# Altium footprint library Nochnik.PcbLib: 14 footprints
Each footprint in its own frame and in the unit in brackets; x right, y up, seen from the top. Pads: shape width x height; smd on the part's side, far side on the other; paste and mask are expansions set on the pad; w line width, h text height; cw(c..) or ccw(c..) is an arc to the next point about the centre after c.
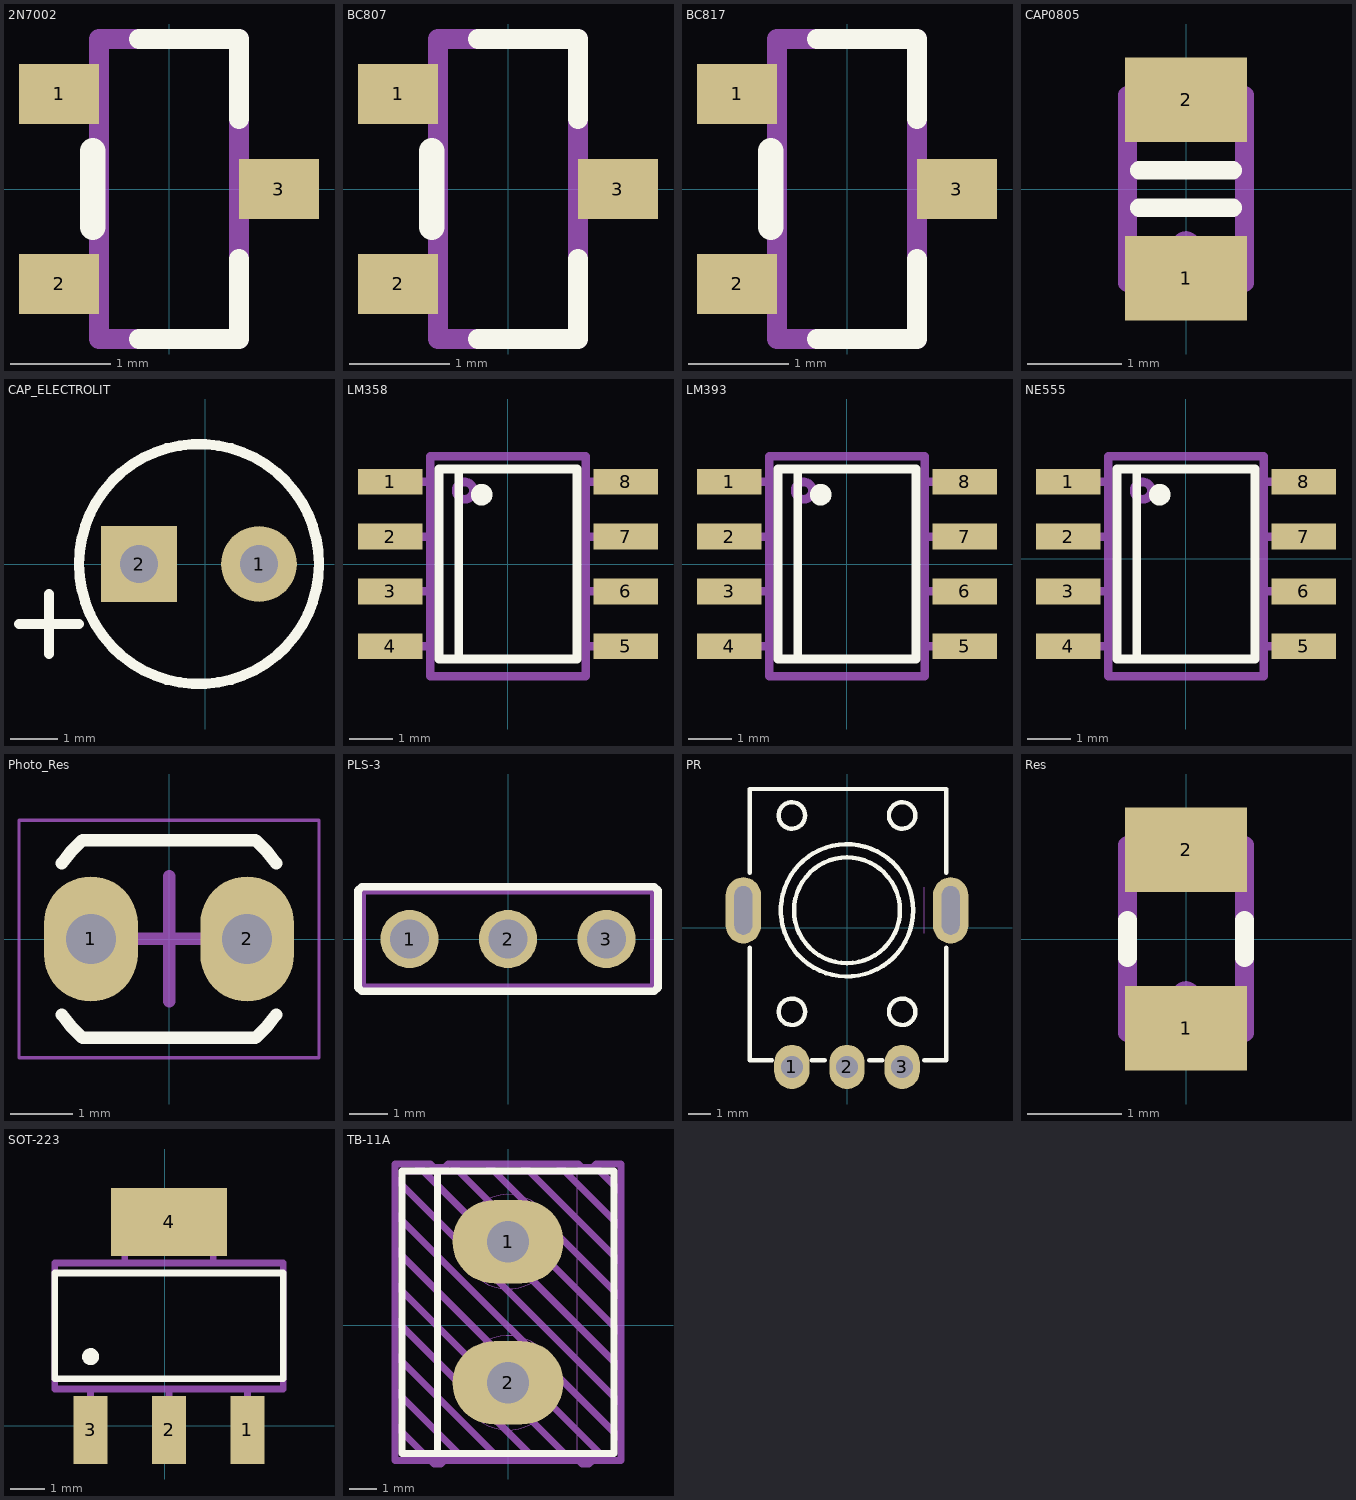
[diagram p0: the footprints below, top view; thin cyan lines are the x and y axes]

## 2N7002 [mm]
pads (3):
  rect 0.8x0.6 smd: 1(-1.1,0.95) 2(-1.1,-0.95) 3(1.1,0)
Top Overlay:
  lines w0.2: -0.3,-1.5 0.7,-1.5 0.7,-0.7 ; -0.3,1.5 0.7,1.5 0.7,0.7
  lines w0.254: -0.762,-0.381 -0.762,0.381
Mechanical 1:
  lines w0.2: -1.2,-0.95 -0.7,-0.95 ; -1.2,0.95 -0.7,0.95 ; 0.7,0 1.2,0 ; -0.7,-1.5 0.7,-1.5 0.7,1.5 -0.7,1.5 -0.7,-1.5
  text ".Designator" at -0.9,1.8 h0.8
3D body "SOT23.step": height 1.1, standoff 0, extent -1.25,-1.5 1.25,1.5

## BC807 [mm]
pads (3):
  rect 0.8x0.6 smd: 1(-1.1,0.95) 2(-1.1,-0.95) 3(1.1,0)
Top Overlay:
  lines w0.2: -0.3,-1.5 0.7,-1.5 0.7,-0.7 ; -0.3,1.5 0.7,1.5 0.7,0.7
  lines w0.254: -0.762,-0.381 -0.762,0.381
Mechanical 1:
  lines w0.2: -1.2,-0.95 -0.7,-0.95 ; -1.2,0.95 -0.7,0.95 ; 0.7,0 1.2,0 ; -0.7,-1.5 0.7,-1.5 0.7,1.5 -0.7,1.5 -0.7,-1.5
  text ".Designator" at -0.9,1.8 h0.8
3D body "SOT23.step": height 1.1, standoff 0, extent -1.25,-1.5 1.25,1.5

## BC817 [mm]
pads (3):
  rect 0.8x0.6 smd: 1(-1.1,0.95) 2(-1.1,-0.95) 3(1.1,0)
Top Overlay:
  lines w0.2: -0.3,-1.5 0.7,-1.5 0.7,-0.7 ; -0.3,1.5 0.7,1.5 0.7,0.7
  lines w0.254: -0.762,-0.381 -0.762,0.381
Mechanical 1:
  lines w0.2: -1.2,-0.95 -0.7,-0.95 ; -1.2,0.95 -0.7,0.95 ; 0.7,0 1.2,0 ; -0.7,-1.5 -0.7,1.5 0.7,1.5 0.7,-1.5 -0.7,-1.5
  text ".Designator" at -0.9,1.8 h0.8
3D body "SOT23.step": height 1.1, standoff 0, extent -1.25,-1.5 1.25,1.5

## CAP0805 [mm]
pads (2):
  rect 1.3x0.9 smd: 1(0,-0.95) 2(0,0.95)
Top Overlay:
  lines w0.2: -0.5,-0.2 0.5,-0.2 ; -0.5,0.2 0.5,0.2
Mechanical 1:
  circle w0.1: c0,-0.6 r0.1
  lines w0.2: -0.625,-1 0.625,-1 0.625,1 -0.625,1 -0.625,-1
  text ".Designator" at -0.7,1.5 h0.8
3D body: height 0.8, standoff 0, extent -0.675,-0.5 0.675,0.5
3D body: height 0.8, standoff 0, extent -0.675,0.5 0.675,1.05
3D body: height 0.8, standoff 0, extent -0.675,-1.05 0.675,-0.5

## CAP_ELECTROLIT [mm]
pads (2):
  round 1.6 hole 0.8: 1(1.143,0)
  rect 1.6x1.6 hole 0.8: 2(-1.397,0)
Top Overlay:
  circle w0.22: c-0.127,0 r2.54
  lines w0.22: -3.937,-1.27 -2.667,-1.27 ; -3.302,-1.905 -3.302,-0.635
3D body "User Library-Capacitor Electrolitico 5x11.step": height 11.9, standoff -1.7, extent -2.627,-2.5 2.373,2.5

## LM358 [mm]
pads (8):
  rect 1.5x0.6 smd: 1(-2.725,1.905) 2(-2.725,0.635) 3(-2.725,-0.635) 4(-2.725,-1.905) 5(2.725,-1.905) 6(2.725,-0.635) 7(2.725,0.635) 8(2.725,1.905)
Top Overlay:
  circle w0.25: c-0.608,1.605 r0.125
  lines w0.2: -1.143,-2.2 -1.143,2.2 ; -1.6,-2.2 1.6,-2.2 1.6,2.2 -1.6,2.2 -1.6,-2.2
Mechanical 1:
  circle w0.2: c-1,1.7 r0.2
  lines w0.2: -2.8,-1.905 -1.8,-1.905 ; -2.8,-0.635 -1.8,-0.635 ; -2.8,0.635 -1.8,0.635 ; -2.8,1.905 -1.8,1.905 ; 1.8,-1.905 2.8,-1.905 ; 1.8,-0.635 2.8,-0.635 ; 1.8,0.635 2.8,0.635 ; 1.8,1.905 2.8,1.905 ; -1.8,-2.6 -1.8,2.5 1.8,2.5 1.8,-2.6 -1.8,-2.6
  text ".Designator" at -1.801,2.819 h0.8
3D body "SOIC-88.step": height 1.75, standoff 0, extent -3,-2.5 3,2.5

## LM393 [mm]
pads (8):
  rect 1.5x0.6 smd: 1(-2.725,1.905) 2(-2.725,0.635) 3(-2.725,-0.635) 4(-2.725,-1.905) 5(2.725,-1.905) 6(2.725,-0.635) 7(2.725,0.635) 8(2.725,1.905)
Top Overlay:
  circle w0.25: c-0.608,1.605 r0.125
  lines w0.2: -1.143,-2.2 -1.143,2.2 ; -1.6,-2.2 -1.6,2.2 1.6,2.2 1.6,-2.2 -1.6,-2.2
Mechanical 1:
  circle w0.2: c-1,1.7 r0.2
  lines w0.2: -2.8,-1.905 -1.8,-1.905 ; -2.8,-0.635 -1.8,-0.635 ; -2.8,0.635 -1.8,0.635 ; -2.8,1.905 -1.8,1.905 ; 1.8,-1.905 2.8,-1.905 ; 1.8,-0.635 2.8,-0.635 ; 1.8,0.635 2.8,0.635 ; 1.8,1.905 2.8,1.905 ; -1.8,-2.6 1.8,-2.6 1.8,2.5 -1.8,2.5 -1.8,-2.6
  text ".Designator" at -1.801,2.819 h0.8
3D body "SOIC-88.step": height 1.75, standoff 0, extent -3,-2.5 3,2.5

## NE555 [mm]
pads (8):
  rect 1.5x0.6 smd: 1(-2.725,1.778) 2(-2.725,0.508) 3(-2.725,-0.762) 4(-2.725,-2.032) 5(2.725,-2.032) 6(2.725,-0.762) 7(2.725,0.508) 8(2.725,1.778)
Top Overlay:
  circle w0.25: c-0.608,1.478 r0.125
  lines w0.2: -1.143,-2.327 -1.143,2.073 ; -1.6,-2.327 1.6,-2.327 1.6,2.073 -1.6,2.073 -1.6,-2.327
Mechanical 1:
  circle w0.2: c-1,1.573 r0.2
  lines w0.2: -2.8,-2.032 -1.8,-2.032 ; -2.8,-0.762 -1.8,-0.762 ; -2.8,0.508 -1.8,0.508 ; -2.8,1.778 -1.8,1.778 ; 1.8,-2.032 2.8,-2.032 ; 1.8,-0.762 2.8,-0.762 ; 1.8,0.508 2.8,0.508 ; 1.8,1.778 2.8,1.778 ; -1.8,-2.727 -1.8,2.373 1.8,2.373 1.8,-2.727 -1.8,-2.727
  text ".Designator" at -1.801,2.692 h0.8
3D body "SOIC-88.step": height 1.75, standoff 0, extent -3,-2.627 3,2.373

## Photo_Res [mm]
pads (2):
  oval 1.5x2 hole 0.8: 1(-1.25,0) 2(1.25,0)
Top Overlay:
  lines w0.2: -1.716,-1.211 ccw(c0,0) -1.383,-1.58 1.383,-1.58 ccw(c0,0) 1.716,-1.211 ; -1.716,1.211 cw(c0,0) -1.383,1.58 1.383,1.58 cw(c0,0) 1.716,1.211
Mechanical 15:
  lines w0.05: -2.4,-1.9 -2.4,1.9 2.4,1.9 2.4,-1.9 -2.4,-1.9
  lines w0.2: -1,0 1,0 ; 0,-1 0,1
3D body "Advanced Photonix NSL-19M51.step": height 1.8, standoff -2.65, extent -2.15,-1.65 2.15,1.65

## PLS-3 [mm]
pads (3):
  round 1.5 hole 1: 1(-2.54,0) 2(0,0) 3(2.54,0)
Top Overlay:
  lines w0.2: -3.87,-1.25 -3.87,1.25 -3.77,1.35 3.77,1.35 3.87,1.25 3.87,-1.25 3.77,-1.35 -3.77,-1.35 -3.87,-1.25
Mechanical 1:
  lines w0.2: -3.77,-1.25 3.77,-1.25 3.77,1.25 -3.77,1.25 -3.77,-1.25
  text ".Designator" at -3.769,1.533 h0.8
3D body: height 1.25, standoff -1.5, extent 2.159,-0.318 2.921,0.318
3D body: height 1.25, standoff -1.5, extent -2.921,-0.318 -2.159,0.318
3D body: height 1.25, standoff -1.5, extent -0.381,-0.318 0.381,0.318
3D body "FEMALE-2.54-3P.SLDPRT": height 8.4, standoff 0, extent -3.71,-1.2 3.81,1.2

## PR [mm]
pads (5):
  oval 1.6x2 / inner round 1.4 / far side oval 1.6x2 hole 1: 1(-2.5,-6.3) 2(0,-6.3) 3(2.5,-6.3)
  oval 1.6x3 hole 0.8 slot 2.2 at 90 deg: ""(-4.7,0.8) ""(4.7,0.8)
Top Overlay:
  circle w0.2: c-2.5,-3.8 r0.6
  circle w0.2: c2.5,-3.8 r0.6
  circle w0.2: c-2.5,5.1 r0.6
  circle w0.2: c2.5,5.1 r0.6
  circle w0.2: c0,0.8 r3
  circle w0.2: c0,0.8 r2.4
  lines w0.2: -4.4,-0.9 -4.4,-6 -3.4,-6 ; -4.4,2.5 -4.4,6.3 4.5,6.3 4.5,2.5 ; -1.6,-6 -1,-6 ; 1,-6 1.6,-6 ; 3.5,-6 4.5,-6 4.5,-0.9
Mechanical 1:
  lines w0.008: 3.5,-0.25 3.5,1.85
3D body "User Library-RV09ACF-40_RK09K1130A5R.step": height 20.1, standoff -3.7, extent -4.902,-6.428 4.849,6.122

## Res [mm]
pads (2):
  rect 1.3x0.9 smd: 1(0,-0.95) 2(0,0.95)
Top Overlay:
  lines w0.2: -0.625,-0.2 -0.625,0.2 ; 0.625,-0.2 0.625,0.2
Mechanical 1:
  circle w0.1: c0,-0.6 r0.1
  lines w0.2: -0.625,-1 -0.625,1 0.625,1 0.625,-1 -0.625,-1
  text ".Designator" at -0.7,1.5 h0.8
3D body: height 0.4, standoff 0, extent -0.65,-1.05 0.65,-0.65
3D body: height 0.4, standoff 0, extent -0.65,0.65 0.65,1.05
3D body: height 0.4, standoff 0, extent -0.65,-0.65 0.65,0.65

## SOT-223 [mm]
pads (4):
  rect 1x2 smd: 1(2.427,-0.129) 2(0.127,-0.129) 3(-2.173,-0.129)
  rect 3.4x2 smd: 4(0.127,5.971)
Top Overlay:
  circle w0.25: c-2.173,2.021 r0.125
  lines w0.2: -3.223,1.371 -3.223,4.471 3.477,4.471 3.477,1.371 -3.223,1.371
Mechanical 1:
  lines w0.2: -2.173,-0.129 -2.173,1.021 ; -1.173,4.821 -1.173,6.421 1.427,6.421 1.427,4.821 ; 0.127,-0.129 0.127,1.021 ; 2.427,-0.129 2.427,1.021 ; -3.223,1.071 -3.223,4.771 3.477,4.771 3.477,1.071 -3.223,1.071
  text ".Designator" at -3.573,1.021 h0.8
3D body "SOT223.step": height 1.8, standoff 0, extent -3.223,-0.579 3.477,6.421

## TB-11A [mm]
pads (2):
  oval 4x3 hole 1.5: 1(0,3) 2(0,-2.08)
Top Overlay:
  lines w0.254: -2.54,-4.62 -2.54,5.54 -3.81,5.54 ; -3.81,5.54 3.81,5.54 3.81,-4.62 -3.81,-4.62 -3.81,5.54
Mechanical 2:
  lines w0.254: -4.064,-1.064 -0.254,-4.874 ; -4.064,5.286 4.064,-2.842 4.064,-4.112 -4.064,4.016 -4.064,2.746 3.556,-4.874 ; -3.302,5.794 4.064,-1.572 4.064,-0.302 -1.778,5.54 -2.032,5.794 ; -2.286,-4.874 -2.413,-5.001 -2.667,-5.001 -2.794,-4.874 ; -1.524,-4.874 -4.064,-2.334 -4.064,-3.604 ; -0.762,5.794 -0.635,5.667 4.064,0.968 4.064,2.238 0.508,5.794 ; 0.381,-4.874 4.064,-4.874 4.064,5.794 3.302,5.794 3.175,5.794 ; 0.635,-4.874 -0.381,-4.874 -1.778,-4.874 -4.064,-4.874 -4.064,5.794 -2.794,5.794 -2.667,5.667 -2.286,5.667 -2.159,5.794 -1.27,5.794 1.905,5.794 2.54,5.794 2.667,5.667 3.048,5.667 3.175,5.794 ; 1.016,-4.874 -4.064,0.206 -4.064,1.476 2.286,-4.874 ; 1.778,5.794 4.064,3.508 4.064,4.778 3.175,5.667 3.175,5.794 ; 2.54,-4.874 2.667,-5.001 2.921,-5.001 3.048,-4.874 ; -4.064,-3.604 -2.794,-4.874 ; -4.064,-3.604 -2.794,-4.874
Mechanical 5:
  circle w0.025: c0,-2.08 r1.7
  circle w0.025: c0,3 r1.7
  lines w0.025: -3.81,5.451 -3.81,5.451 ; -3.81,5.451 -3.81,-4.645 2.5,-4.645 ; -3.81,5.451 2.5,5.451 ; 2.5,-4.645 2.5,-4.645 ; 2.5,-4.645 2.5,5.451 ; 2.5,5.451 2.5,5.451
3D body: height 10, standoff 6, extent 2.5,-4.645 4.064,5.452
3D body: height 6, standoff 5, extent 3.048,-2.715 4.064,-1.445
3D body: height 6, standoff 5, extent 3.048,2.365 4.064,3.635
3D body: height 9.1, standoff 4.99, extent -3.81,-4.645 2.5,5.451
3D body: height 1.52, standoff -1.78, extent -0.381,-2.588 0.381,-1.572
3D body: height 1.52, standoff -1.78, extent -0.381,2.492 0.381,3.508
3D body: height 6, standoff 1.49, extent 2.032,-3.858 4.064,-2.588
3D body: height 6, standoff 1.49, extent 2.032,-1.572 4.064,-0.302
3D body: height 6, standoff 1.49, extent 2.032,1.222 4.064,2.492
3D body: height 6, standoff 1.49, extent 2.032,3.508 4.064,4.778
3D body: height 1.5, standoff 0, extent 2.032,-3.858 4.064,-0.302
3D body: height 1.5, standoff 0, extent -3.81,-3.858 -2.794,-0.302
3D body: height 1.5, standoff 0, extent -3.81,1.222 -2.794,4.778
3D body: height 6, standoff 0, extent 2.921,5.324 4.064,5.451
3D body: height 6, standoff 0, extent -2.413,5.324 2.667,5.451
3D body: height 6, standoff 0, extent -3.81,5.324 -2.667,5.451
3D body: height 6, standoff 0, extent -3.81,4.778 4.064,5.337
3D body: height 6, standoff 0, extent -3.81,-4.645 4.064,-3.858
3D body: height 6, standoff 0, extent -3.81,-0.302 4.064,1.222
3D body: height 5.1, standoff 4.9, extent -2.794,1.222 2.032,4.778
3D body: height 5, standoff 0.49, extent -2.794,1.222 1.778,1.476
3D body: height 5, standoff 0.49, extent 1.778,1.222 2.032,4.778
3D body: height 5, standoff 0.49, extent -2.794,4.524 1.778,4.778
3D body: height 1.6, standoff 1.5, extent -2.794,1.476 1.778,4.524
3D body: height 1.6, standoff 1.5, extent -2.794,-3.604 1.778,-0.556
3D body: height 5, standoff 0.49, extent -2.794,-0.556 1.778,-0.302
3D body: height 5, standoff 0.49, extent 1.778,-3.858 2.032,-0.302
3D body: height 5, standoff 0.49, extent -2.794,-3.858 1.778,-3.604
3D body: height 5.1, standoff 4.9, extent -2.794,-3.858 2.032,-0.302
3D body: height 5.9, standoff 0, extent -2.794,-4.76 -2.286,-4.633
3D body: height 5.9, standoff 0, extent 2.54,-4.76 3.048,-4.633
3D body: height 1.5, standoff 0, extent 2.032,1.222 4.064,4.778
3D body: height 9.3, standoff 9, extent -1.5,-3.58 1.5,-0.58
3D body: height 10, standoff 9, extent -3.81,-4.58 2.5,0.5
3D body: height 9.8, standoff 9.2, extent -1.6,-3.68 1.6,-0.48
3D body: height 9.3, standoff 9, extent -1.5,1.501 1.5,4.5
3D body: height 10, standoff 9, extent -3.81,0.5 2.5,5.451
3D body: height 9.8, standoff 9.2, extent -1.6,1.4 1.6,4.6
